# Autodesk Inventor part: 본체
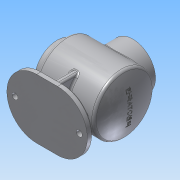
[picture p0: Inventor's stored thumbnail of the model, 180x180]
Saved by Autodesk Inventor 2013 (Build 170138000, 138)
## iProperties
Created: 2016-04
Part Number: 본체
Material: 알루미늄 6061
Document SubType Name: Modeling
Designer: Administrator
Density: 2.71 g/cm^3
Mass: 912.489 g
Surface Area: 1229.6 cm^2
Volume: 336.712 cm^3
Author: Administrator
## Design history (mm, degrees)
sketch "스케치1"
  geometry: L1 (-49, 0)-(-49, 50); L2 (-49, 50)-(50.087, 50); L3 (-49, 0)-(61, 0); A1 r 120 centre (-59, 0) between (61, 0) and (50.087, 50); 2 further points
  constraints: 6 end point, 2 horizontal alignment, 2 point on circle, 1 centre point, 1 coincident, 1 horizontal, 1 parallel, 1 vertical
  dimensions: "d9" = 240 diameter of A1; "d17" = 110 distance of L3.end L1.start; "d24" = 61 distance of L3.end point (0, 0); "d25" = 100 diameter of L2 L3
revolve "회전2" sketch "스케치1" stored, may be unused: angle "d27" = 90 deg
sketch "스케치3"
  geometry: C1 r 50 at (0, 0) reference; C2 r 38 at (0, 0)
  constraints: 1 centre point, 1 coincident
  dimensions: "d28" = 76 diameter of C2
feature "쉘2" dims "d30" = 3
extrude "돌출2" join sketch "스케치3" distance "d31" = 12; taper "d32" = 0 deg
node "작업 평면1"
sketch "스케치5"
  geometry: L1 (49, 50)-(49, -50) reference; C1 r 38 at (-1, 0); 1 further point
  constraints: 1 centre point, 1 horizontal alignment
  dimensions: "d115" = 76 diameter of C1; "d117" = 50 distance from line of L1 C1.centre
extrude "돌출4" join sketch "스케치5" stored distance "d40" = 15; taper "d41" = 0 deg
node "작업 평면2"
sketch "스케치9"
  geometry: L1 (-18.5, -50)-(16.5, -50); L2 (16.5, 50)-(-18.5, 50); A1 r 50 centre (16.5, 0) between (16.5, -50) and (16.5, 50); A2 r 50 centre (-18.5, 0) between (-18.5, 50) and (-18.5, -50); 2 further points
  constraints: 4 end point, 4 point on circle, 3 tangent, 2 centre point, 2 horizontal alignment, 1 coincident, 1 equal radius, 1 horizontal
  dimensions: "d69" = 135 dimension on A2 A1; "d71" = 50 radius of A2; "d159" = 18.5 distance of A2.centre point (0, 0)
extrude "돌출6" join sketch "스케치9" distance "d72" = 10; taper "d73" = 0 deg
sketch "스케치10"
  geometry: L1 (-4, 40)-(6, 40); L2 (6, 40)-(6, -40); L3 (6, -40)-(-4, -40); L4 (-4, -40)-(-4, 40); 2 further points
  constraints: 8 end point, 2 parallel, 1 horizontal, 1 horizontal alignment, 1 midpoint, 1 perpendicular
  dimensions: "d155" = 4 horizontal distance of L1.start point (0, 0); "d156" = 10 distance of L1.start L1.end; "d157" = 80 distance of L1.end L2.end
extrude "돌출7" join sketch "스케치10" stored distance "d77" = 10; taper "d78" = 0 deg
sketch "스케치11"
  geometry: L1 (-61, 38)-(-49, 38) reference; L2 (-61, -38)-(-61, 38) reference; L3 (-46, 47)-(-46, -47) reference; L4 (-46, -47)-(48.145, -47) reference; L5 (48.145, 47)-(-46, 47) reference; L6 (-37, 65)-(39, 65) reference; L7 (39, 50)-(50.087, 50) reference; L8 (50.087, -50)-(6, -50) reference; L9 (6, -69)-(68.5, -69) reference; L10 (68.5, -69)-(68.5, -79) reference; L11 (68.5, -79)-(-66.5, -79) reference; L12 (-66.5, -79)-(-66.5, -69) reference; L13 (-66.5, -69)-(-4, -69) reference; L14 (-4, -50)-(-49, -50) reference; L15 (-49, -50)-(-49, -38) reference; L16 (-49, -38)-(-61, -38) reference; L17 (-49, 38)-(-49, 50) reference; L18 (-49, 50)-(-37, 50) reference; L19 (-35.65, -50)-(-39, -69); L20 (37.65, -50)-(41, -69); L21 (39, 65)-(39, 50) reference; L22 (-37, 50)-(-37, 65) reference; L23 (6, -50)-(6, -69) reference; L24 (-4, -69)-(-4, -50) reference; A1 r 117 centre (-59, 0) between (48.145, -47) and (48.145, 47) reference; A2 r 120 centre (-59, 0) between (50.087, -50) and (50.087, 50) reference; 2 further points
  constraints: 4 end point, 4 point on line, 1 horizontal alignment
  dimensions: "d80" = 100 deg angle of L9 L20; "d82" = 100 deg angle of L13 L19; "d161" = 50 distance from line of L17 point (1, 0); "d162" = 40 horizontal distance of L19.end point (1, 0); "d163" = 40 horizontal distance of point (1, 0) L20.end
  node "절단 모서리 투영1"
feature "리브1" dims "d83" = 1, "d84" = 10, "d85" = 0, "d86" = 0, "d87" = 1, "d88" = 1
feature "리브2" dims "d89" = 1, "d90" = 10, "d91" = 0, "d92" = 0, "d93" = 1, "d94" = 1
fillet "모깎기1" dims "d95" = 2
fillet "모깎기2" dims "d96" = 5
fillet "모깎기4" dims "d98" = 3
chamfer "모따기1" distance "d99" = 3; stored, may be unused: second distance "d100" = 2, angle "d101" = 45 deg
sketch "스케치12"
  geometry: C1 r 5 at (-53, 0); 1 further point
  constraints: 1 centre point, 1 horizontal alignment
  dimensions: "d102" = 10 diameter of C1; "d104" = 53 distance of C1.centre point (0, 0)
extrude "돌출8" cut sketch "스케치12" stored distance "d105" = 10; taper "d106" = 0 deg
node "작업 평면3"
sketch "스케치13"
  geometry: 2 further points
  constraints: 1 coincident, 1 other
feature "엠보싱1" sketch "스케치13" dims "d9" = 240, "d17" = 110, "d24" = 61, "d25" = 100, "d110" = 0.5, "d111" = 0
sketch "스케치14"
  geometry: C1 r 38 at (0, 0) reference; C2 r 27 at (0, 0)
  constraints: 1 centre point, 1 coincident
  dimensions: "d118" = 54 diameter of C2
extrude "돌출9" cut sketch "스케치14" stored distance "d120" = 10; taper "d121" = 0 deg
sketch "스케치15"
  geometry: C1 r 27 at (0, 0) reference; 1 further point
  constraints: 1 vertical alignment
  dimensions: "d122" = 32.5 distance of C1.centre point (0, 32.5)
hole "구멍3" sketch "스케치15" at (0, 32.5) diameter "d123" = 3.242; stored, may be unused: countersink angle "d127" = 90 deg, drill point angle "d129" = 118 deg; dims "d124" = 8, "d125" = 4, "d126" = 2, "d128" = 10
chamfer "모따기3" distance "d133" = 1; stored, may be unused: second distance "d134" = 2, angle "d135" = 45 deg
sketch "스케치16"
  geometry: C1 r 38 at (0, 0) reference; C2 r 27 at (0, 0)
  constraints: 1 centre point, 1 coincident
  dimensions: "d136" = 54 diameter of C2
extrude "돌출10" cut sketch "스케치16" distance "d138" = 48; taper "d139" = 0 deg
sketch "스케치17"
  geometry: C1 r 27 at (0, 0) reference; 1 further point
  constraints: 1 vertical alignment
  dimensions: "d140" = 32.5 distance of C1.centre point (0, 32.5)
hole "구멍4" sketch "스케치17" at (0, 32.5) diameter "d141" = 3.242; stored, may be unused: countersink angle "d145" = 90 deg, drill point angle "d147" = 118 deg; dims "d142" = 8, "d143" = 4, "d144" = 2, "d146" = 10
chamfer "모따기4" distance "d151" = 1; stored, may be unused: second distance "d152" = 2, angle "d153" = 45 deg
fillet "모깎기5" dims "d154" = 3
fillet "모깎기6" dims "d164" = 5
fillet "모깎기7" dims "d165" = 3
node "솔리드2"
pattern_linear "직사각형 패턴1" dims "d109" = 108
pattern_circular "원형 패턴3" dims angle "d131" = 360 deg
pattern_circular "원형 패턴4" dims angle "d149" = 360 deg
other parameters: "d37" = 65, "d68" = -79
